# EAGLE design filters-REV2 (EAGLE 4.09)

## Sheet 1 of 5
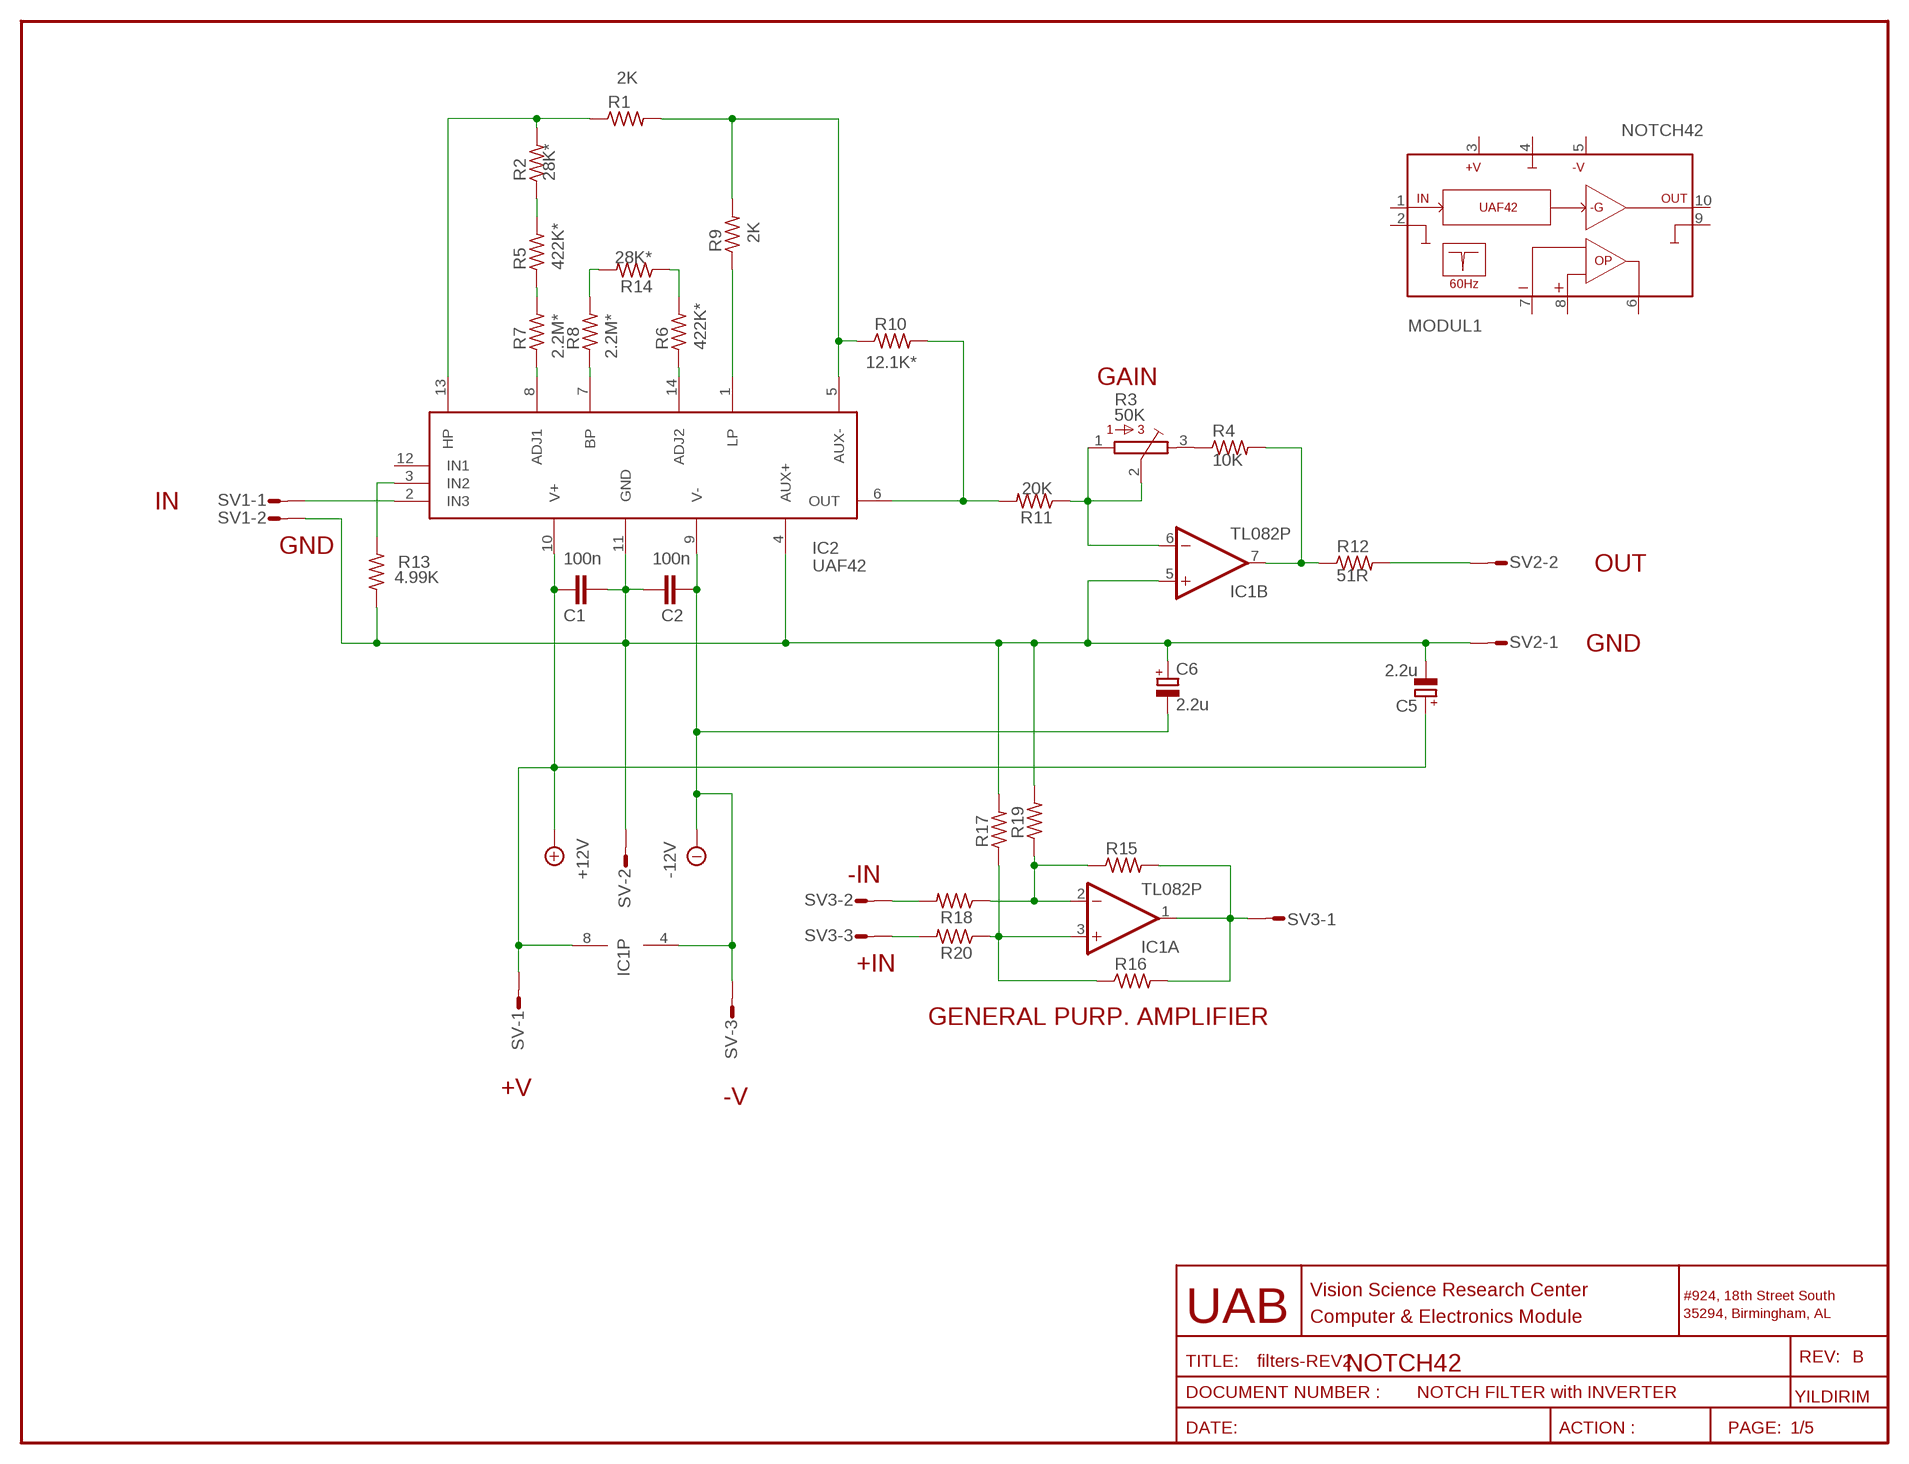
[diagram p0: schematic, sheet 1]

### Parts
C1  100n  C-EU050-025X075  [C050-025X075]
C2  100n  C-EU050-025X075  [C050-025X075]
C5  2.2u  CPOL-EUE2.5-5  [E2,5-5]
C6  2.2u  CPOL-EUE2.5-5  [E2,5-5]
IC1  TL082P  [DIL08]
IC2  UAF42  [DIP-14]
MODUL1  NOTCH42  [NOTCH42]
R1  2K  R-US_0207/10  [0207/10]
R2  28K*  R-US_0207/10  [0207/10]
R3  50K  B25P  [B25P@2]
R4  10K  R-US_0207/10  [0207/10]
R5  422K*  R-US_0207/10  [0207/10]
R6  422K*  R-US_0207/10  [0207/10]
R7  2.2M*  R-US_0207/10  [0207/10]
R8  2.2M*  R-US_0207/10  [0207/10]
R9  2K  R-US_0207/10  [0207/10]
R10  12.1K*  R-US_0207/10  [0207/10]
R11  20K  R-US_0207/10  [0207/10]
R12  51R  R-US_0207/10  [0207/10]
R13  4.99K  R-US_0207/10  [0207/10]
R14  28K*  R-US_0207/10  [0207/10]
R15  R-US_0207/10  [0207/10]
R16  R-US_0207/10  [0207/10]
R17  R-US_0207/10  [0207/10]
R18  R-US_0207/10  [0207/10]
R19  R-US_0207/10  [0207/10]
R20  R-US_0207/10  [0207/10]
SV  S03P  [S03P]
SV1  S02P  [S02P]
SV2  S02P  [S02P]
SV3  S03P  [S03P]

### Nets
+12VABI: C1.2 C5.+ IC1.8(P:V+) IC2.10(V+) SV.1 ; supply symbol labelled +12V
-12VABI: C2.1 C6.- IC1.4(P:V-) IC2.9(V-) SV.3 ; supply symbol labelled -12V
N$1: IC2.2(IN3) SV1.1
N$2: R12.2 SV2.2
N$3: R3.3 R4.1
N$4: C1.1 C2.2 C5.- C6.+ IC1.5(B:+IN) IC2.4(AUX+) IC2.11(GND) R13.1 R17.2 R19.2 SV1.2 SV2.1 SV.2
N$5: IC2.8(ADJ1) R7.1
N$6: R5.1 R7.2
N$7: IC2.7(BP) R8.1
N$8: IC1.7(B:OUT) R4.2 R12.1
N$9: IC1.6(B:-IN) R3.1 R3.2 R11.1
N$10: IC2.14(ADJ2) R6.1
N$11: R8.2 R14.2
N$12: R6.2 R14.1
N$13: R2.1 R5.2
N$14: R18.2 SV3.2
N$15: IC1.2(A:-IN) R15.1 R18.1 R19.1
N$16: R20.2 SV3.3
N$18: IC1.1(A:OUT) R15.2 R16.2 SV3.1
N$20: IC1.3(A:+IN) R16.1 R17.1 R20.1
N$52: IC2.3(IN2) R13.2
N$60: IC2.6(OUT) R10.2 R11.2
N$65: IC2.13(HP) R1.1 R2.2
N$68: IC2.5(AUX-) R1.2 R9.2 R10.1
N$69: IC2.1(LP) R9.1
Unconnected: IC2.12(IN1) MODUL1.1(IN) MODUL1.2(GND1) MODUL1.3(+V) MODUL1.4(COMM) MODUL1.5(-V) MODUL1.6(OP-OUT) MODUL1.7(OP-) MODUL1.8(OP+) MODUL1.9(GND2) MODUL1.10(OUT)

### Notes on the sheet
- GAIN
- IN
- GND
- OUT
- GND
- -IN
- +IN
- GENERAL PURP. AMPLIFIER
- +V
- -V
- B
- NOTCH42
- NOTCH FILTER with INVERTER

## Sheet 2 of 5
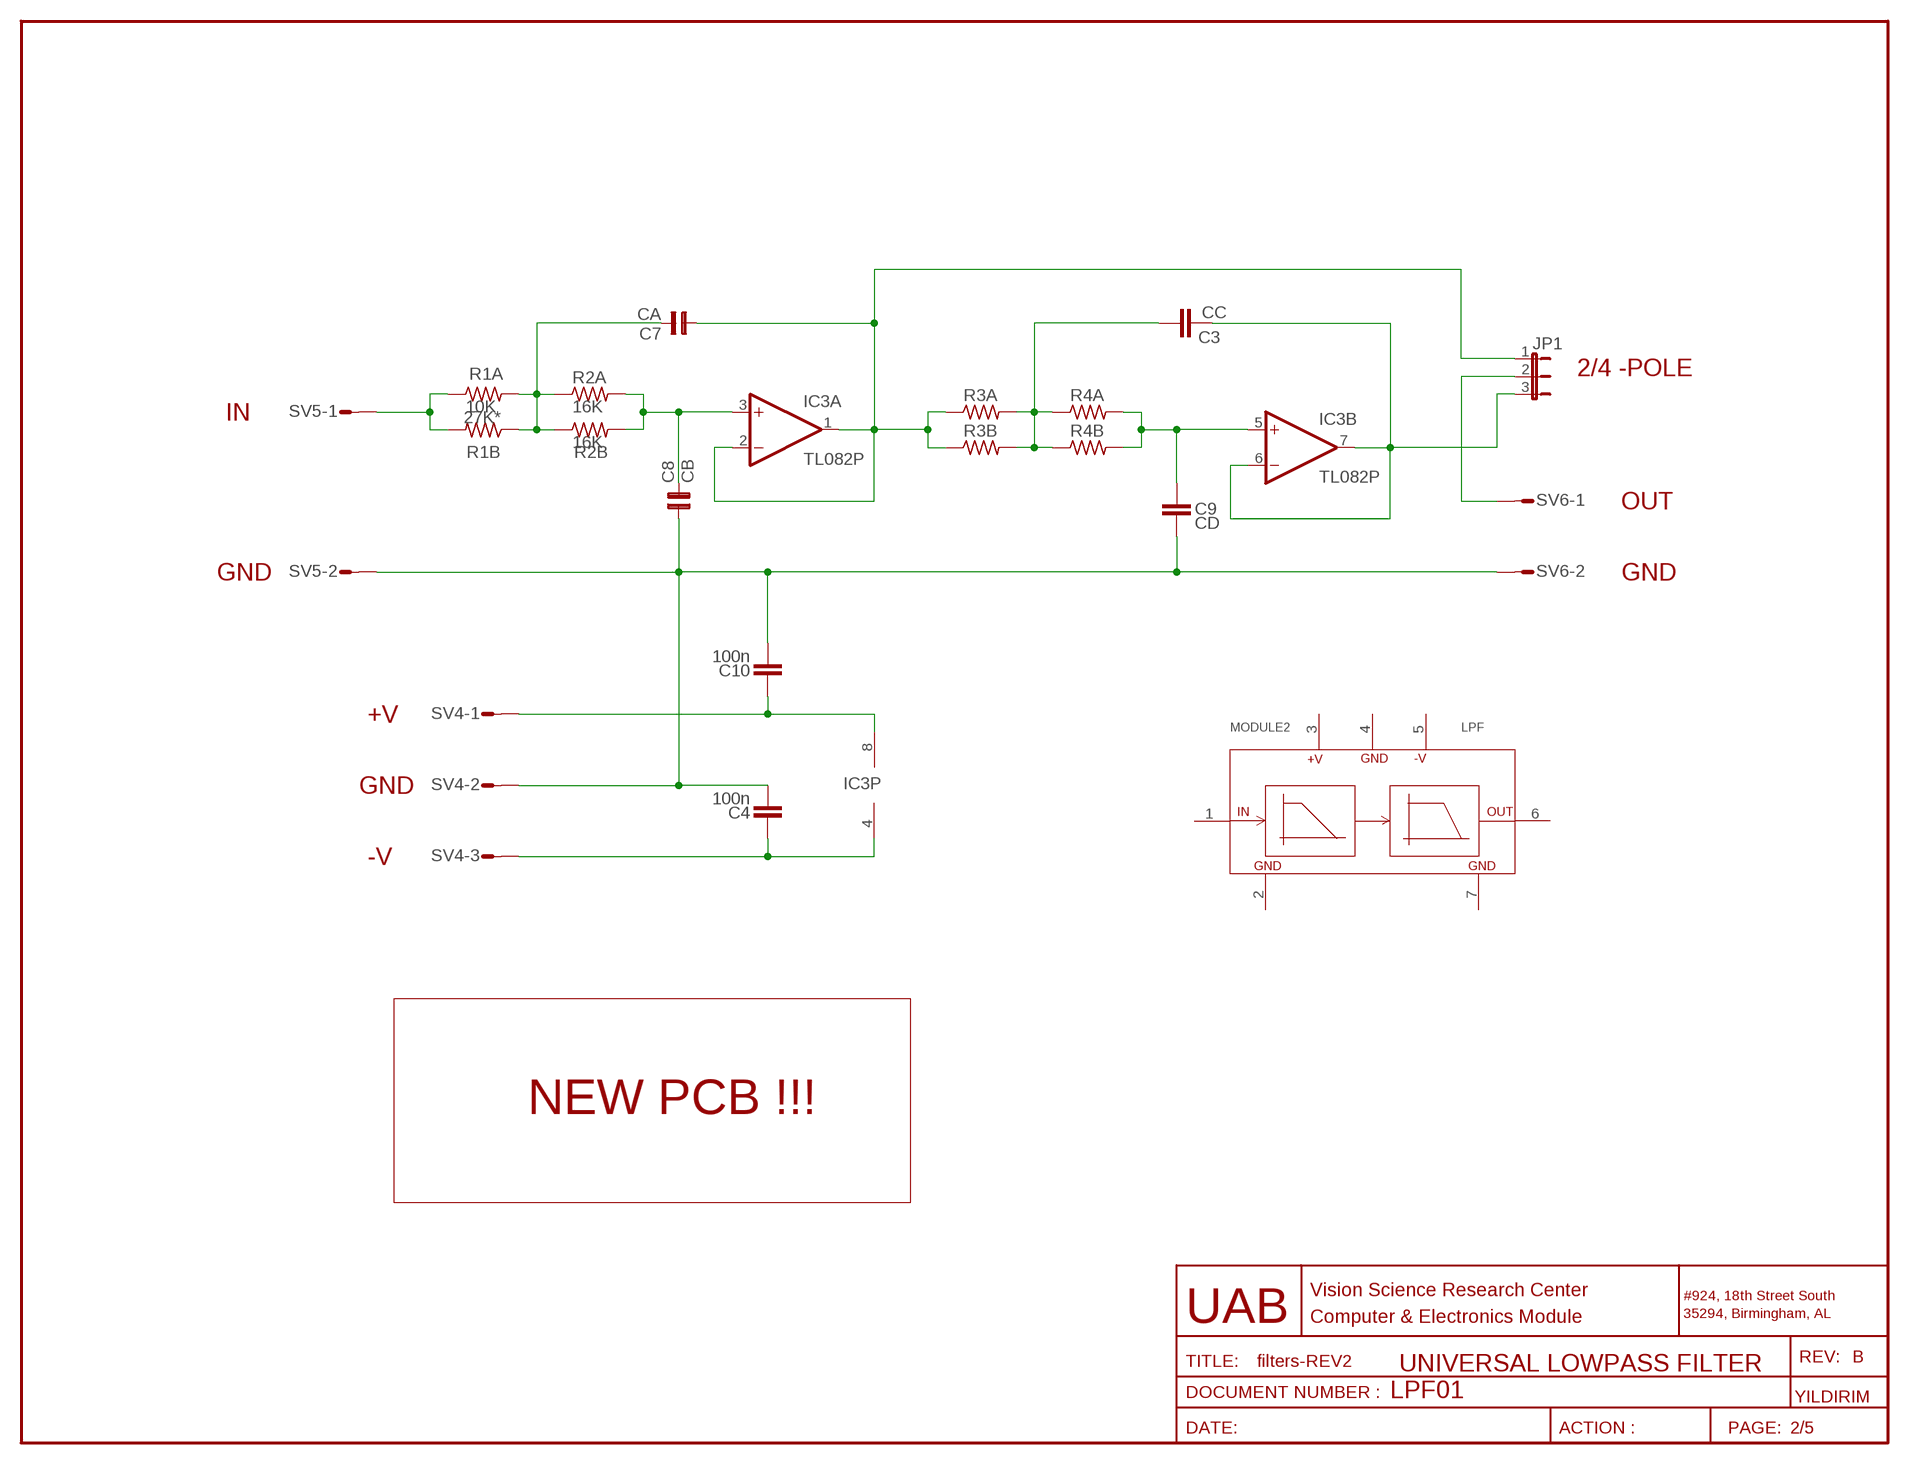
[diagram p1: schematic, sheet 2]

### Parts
C3  CC  C-EU050-025X075  [C050-025X075]
C4  100n  C-EU050-025X075  [C050-025X075]
C7  CA  C5/2.5  [C5B2.5]
C8  CB  C5/2.5  [C5B2.5]
C9  CD  C-EU050-025X075  [C050-025X075]
C10  100n  C-EU050-025X075  [C050-025X075]
IC3  TL082P  [DIL08]
JP1  JP2W  [JP2W]
MODULE2  LPF  [LPF]
R1A  10K  R-US_0207/10  [0207/10]
R1B  27K*  R-US_0207/10  [0207/10]
R2A  16K  R-US_0207/10  [0207/10]
R2B  16K  R-US_0207/10  [0207/10]
R3A  R-US_0207/10  [0207/10]
R3B  R-US_0207/10  [0207/10]
R4A  R-US_0207/10  [0207/10]
R4B  R-US_0207/10  [0207/10]
SV4  S03P  [S03P]
SV5  S02P  [S02P]
SV6  S02P  [S02P]

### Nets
N$17: JP1.2 SV6.1
N$19: C3.1 IC3.6(B:-IN) IC3.7(B:OUT) JP1.3
N$21: C7.2 R1A.2 R1B.1 R2A.1 R2B.1
N$22: C7.1 IC3.1(A:OUT) IC3.2(A:-IN) JP1.1 R3A.1 R3B.1
N$24: C8.2 IC3.3(A:+IN) R2A.2 R2B.2
N$25: C4.1 IC3.4(P:V-) SV4.3
N$26: C10.1 IC3.8(P:V+) SV4.1
N$30: C3.2 R3A.2 R3B.2 R4A.1 R4B.1
N$33: C9.1 IC3.5(B:+IN) R4A.2 R4B.2
N$42: C4.2 C8.1 C9.2 C10.2 SV4.2 SV5.2 SV6.2
SUM-OUT: R1A.1 R1B.2 SV5.1
Unconnected: MODULE2.1 MODULE2.2 MODULE2.3 MODULE2.4 MODULE2.5 MODULE2.6 MODULE2.7

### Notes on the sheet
- 2/4 -POLE
- IN
- OUT
- GND | GND
- +V
- GND
- -V
- NEW PCB !!!
- B
- UNIVERSAL LOWPASS FILTER
- LPF01

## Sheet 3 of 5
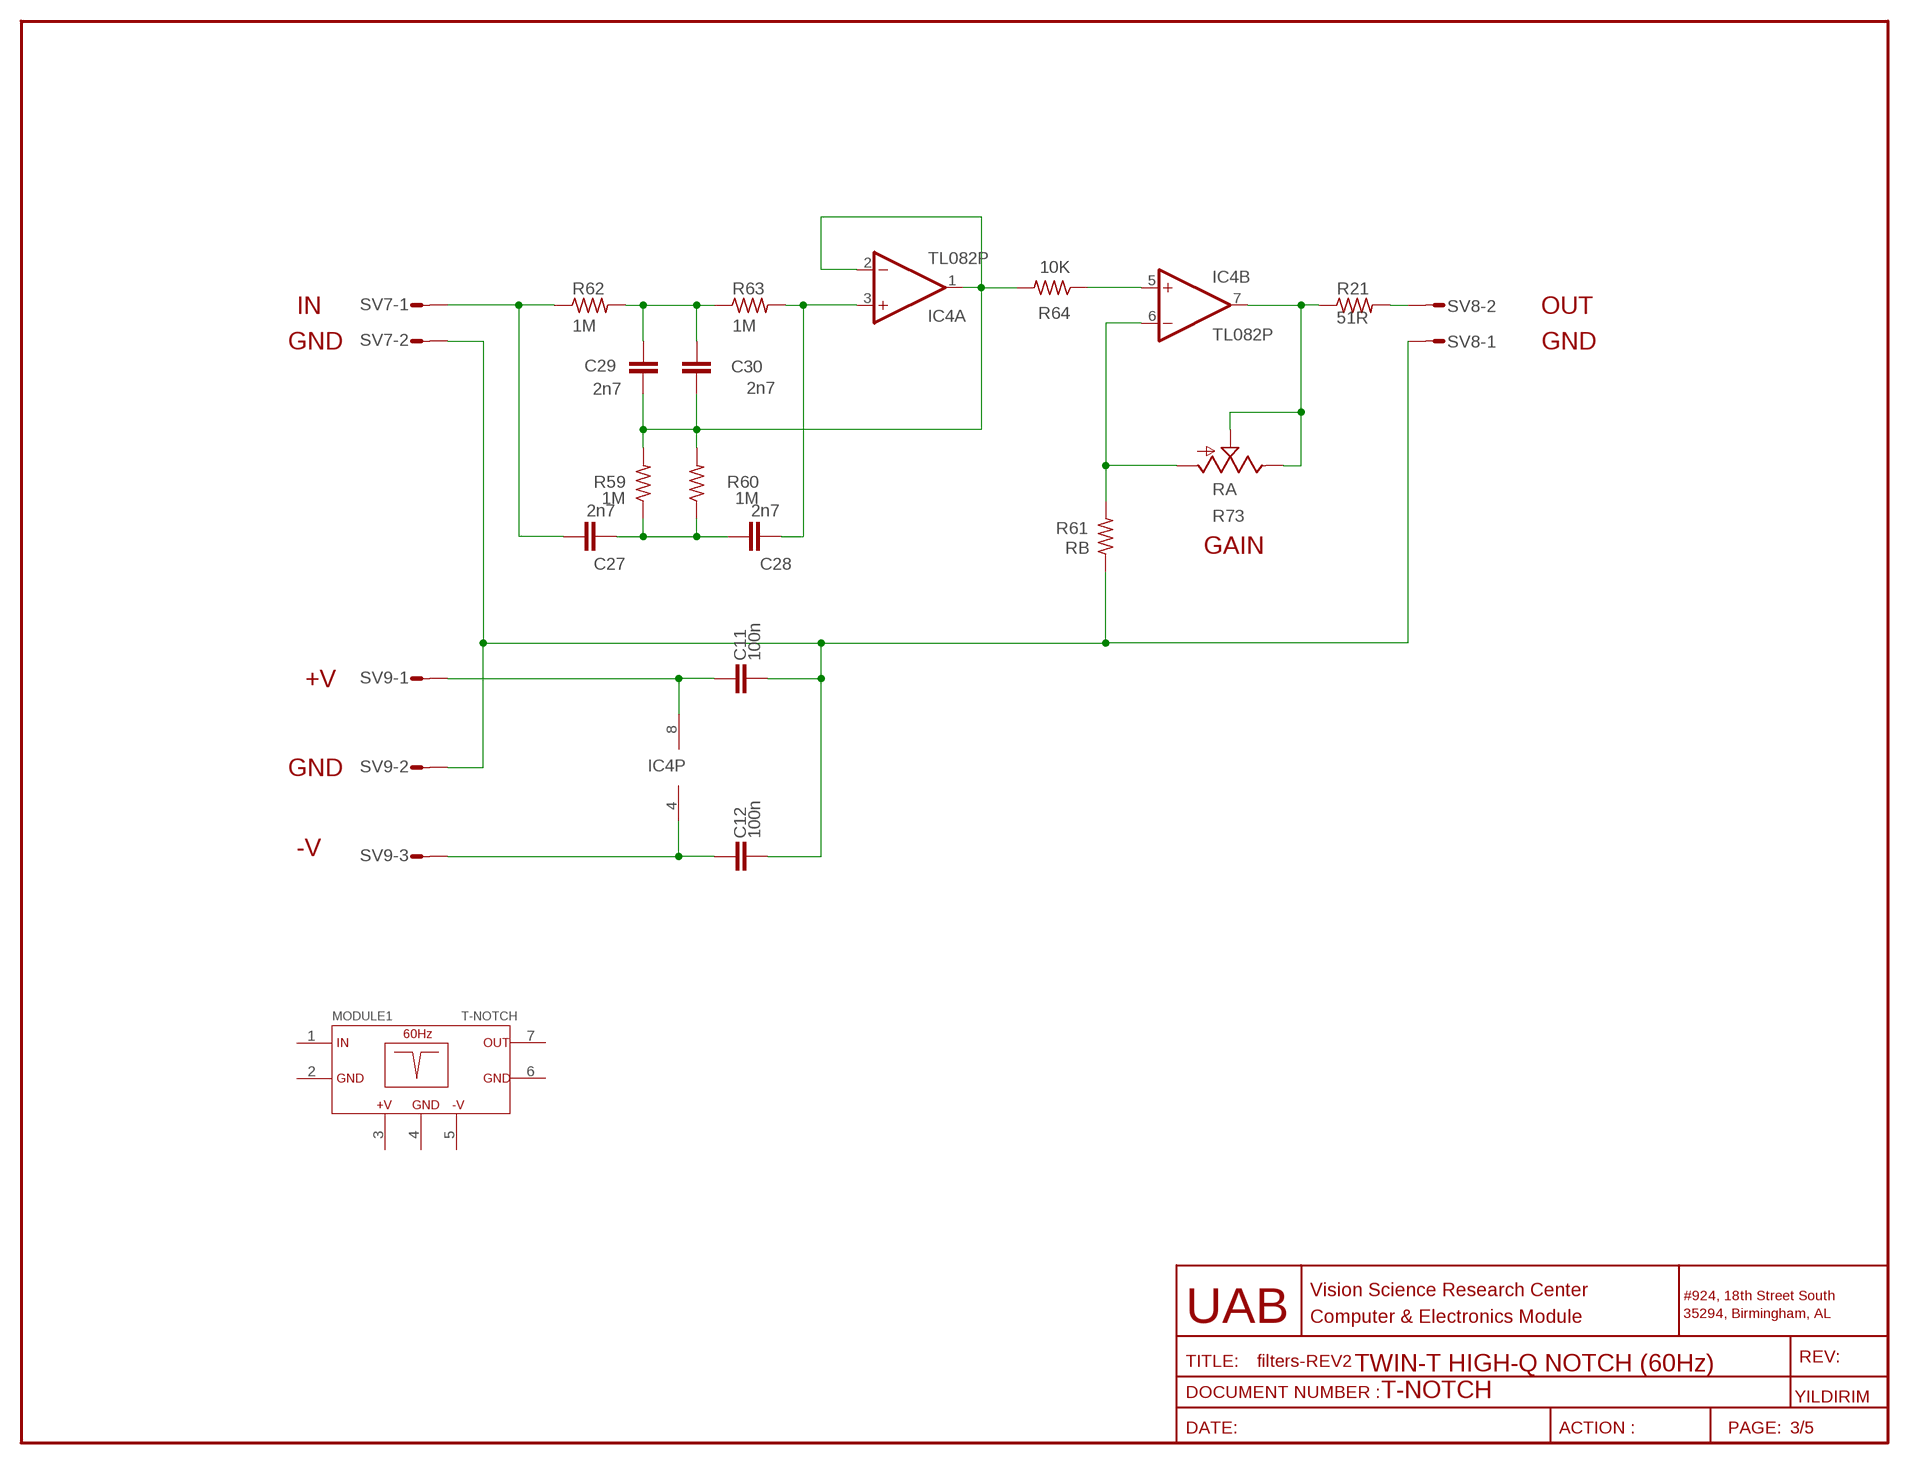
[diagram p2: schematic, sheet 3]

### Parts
C11  100n  C-EU050-025X075  [C050-025X075]
C12  100n  C-EU050-025X075  [C050-025X075]
C27  2n7  C-EU050-025X075  [C050-025X075]
C28  2n7  C-EU050-025X075  [C050-025X075]
C29  2n7  C-EU050-025X075  [C050-025X075]
C30  2n7  C-EU050-025X075  [C050-025X075]
IC4  TL082P  [DIL08]
MODULE1  T-NOTCH  [T-NOTCH]
R21  51R  R-US_0207/10  [0207/10]
R59  1M  R-US_0207/10  [0207/10]
R60  1M  R-US_0207/10  [0207/10]
R61  RB  R-US_0207/10  [0207/10]
R62  1M  R-US_0207/10  [0207/10]
R63  1M  R-US_0207/10  [0207/10]
R64  10K  R-US_0207/10  [0207/10]
R73  RA  TRIM_US-B25P  [B25P]
SV7  S02P  [S02P]
SV8  S02P  [S02P]
SV9  S03P  [S03P]

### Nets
N$23: C11.1 IC4.8(P:V+) SV9.1
N$27: C29.2 C30.2 R62.2 R63.1
N$28: C12.1 IC4.4(P:V-) SV9.3
N$31: C11.2 C12.2 R61.1 SV7.2 SV8.1 SV9.2
N$32: R21.2 SV8.2
N$34: IC4.7(B:OUT) R21.1 R73.E R73.S
N$35: IC4.5(B:+IN) R64.1
N$83: C27.2 R62.1 SV7.1
N$99: IC4.6(B:-IN) R61.2 R73.A
N$102: C27.1 C28.2 R59.1 R60.1
N$106: C28.1 IC4.3(A:+IN) R63.2
N$109: C29.1 C30.1 IC4.1(A:OUT) IC4.2(A:-IN) R59.2 R60.2 R64.2
Unconnected: MODULE1.1(IN) MODULE1.2(GND-IN) MODULE1.3(+V) MODULE1.4(GND) MODULE1.5(-V) MODULE1.6(GND-OUT) MODULE1.7(OUT)

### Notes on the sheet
- IN | OUT
- GND | GND
- GAIN
- +V
- GND
- -V
- TWIN-T HIGH-Q NOTCH (60Hz)
- T-NOTCH

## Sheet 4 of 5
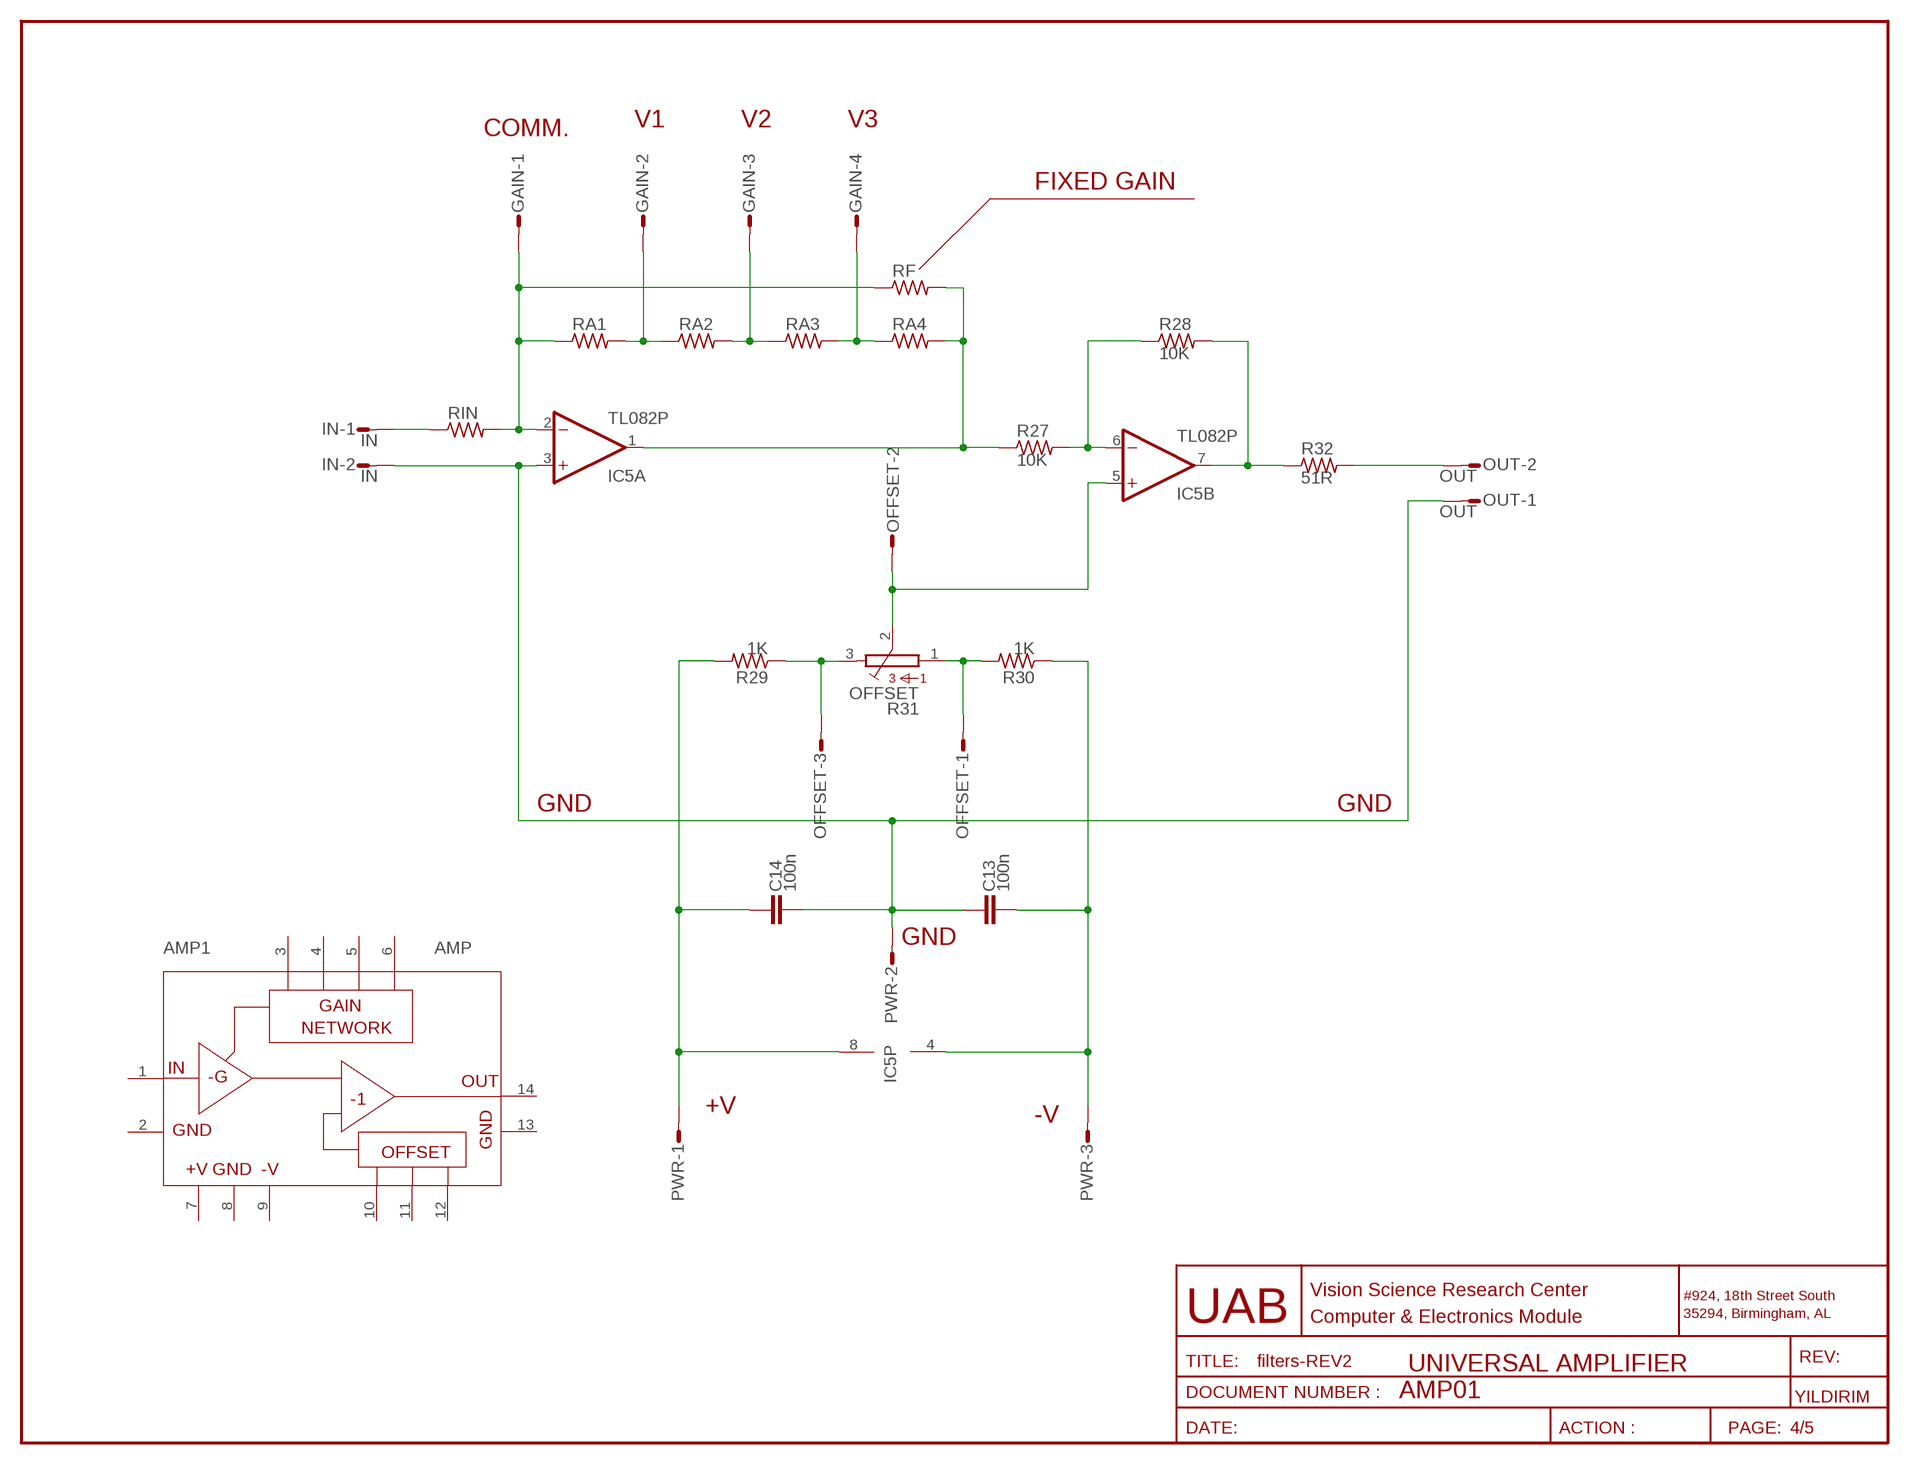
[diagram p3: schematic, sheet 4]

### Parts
AMP1  AMP  [AMP]
C13  100n  C-EU050-025X075  [C050-025X075]
C14  100n  C-EU050-025X075  [C050-025X075]
GAIN  S04P  [S04P]
IC5  TL082P  [DIL08]
IN  IN  S02P  [S02P]
OFFSET  S03P  [S03P]
OUT  OUT  S02P  [S02P]
PWR  S03P  [S03P]
R27  10K  R-US_0207/10  [0207/10]
R28  10K  R-US_0207/10  [0207/10]
R29  1K  R-US_0207/10  [0207/10]
R30  1K  R-US_0207/10  [0207/10]
R31  OFFSET  B25P  [B25P@2]
R32  51R  R-US_0207/10  [0207/10]
RA1  R-US_0207/10  [0207/10]
RA2  R-US_0207/10  [0207/10]
RA3  R-US_0207/10  [0207/10]
RA4  R-US_0207/10  [0207/10]
RF  R-US_0207/10  [0207/10]
RIN  R-US_0207/10  [0207/10]

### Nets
N$29: IN.1 RIN.1
N$36: GAIN.1 IC5.2(A:-IN) RA1.1 RF.1 RIN.2
N$37: GAIN.2 RA1.2 RA2.1
N$38: GAIN.3 RA2.2 RA3.1
N$39: GAIN.4 RA3.2 RA4.1
N$40: OUT.2 R32.2
N$41: C13.2 IC5.4(P:V-) PWR.3 R30.1
N$45: IC5.1(A:OUT) R27.1 RA4.2 RF.2
N$47: IC5.6(B:-IN) R27.2 R28.1
N$49: IC5.7(B:OUT) R28.2 R32.1
N$51: OFFSET.3 R29.1 R31.3
N$53: OFFSET.1 R30.2 R31.1
N$57: IC5.5(B:+IN) OFFSET.2 R31.2
N$58: C14.1 IC5.8(P:V+) PWR.1 R29.2
N$67: C13.1 C14.2 IC5.3(A:+IN) IN.2 OUT.1 PWR.2
Unconnected: AMP1.1 AMP1.2 AMP1.3 AMP1.4 AMP1.5 AMP1.6 AMP1.7 AMP1.8 AMP1.9 AMP1.10 AMP1.11 AMP1.12 AMP1.13 AMP1.14

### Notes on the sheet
- V1 | V2 | V3
- COMM.
- FIXED GAIN
- GND | GND
- GND
- +V
- -V
- UNIVERSAL AMPLIFIER
- AMP01

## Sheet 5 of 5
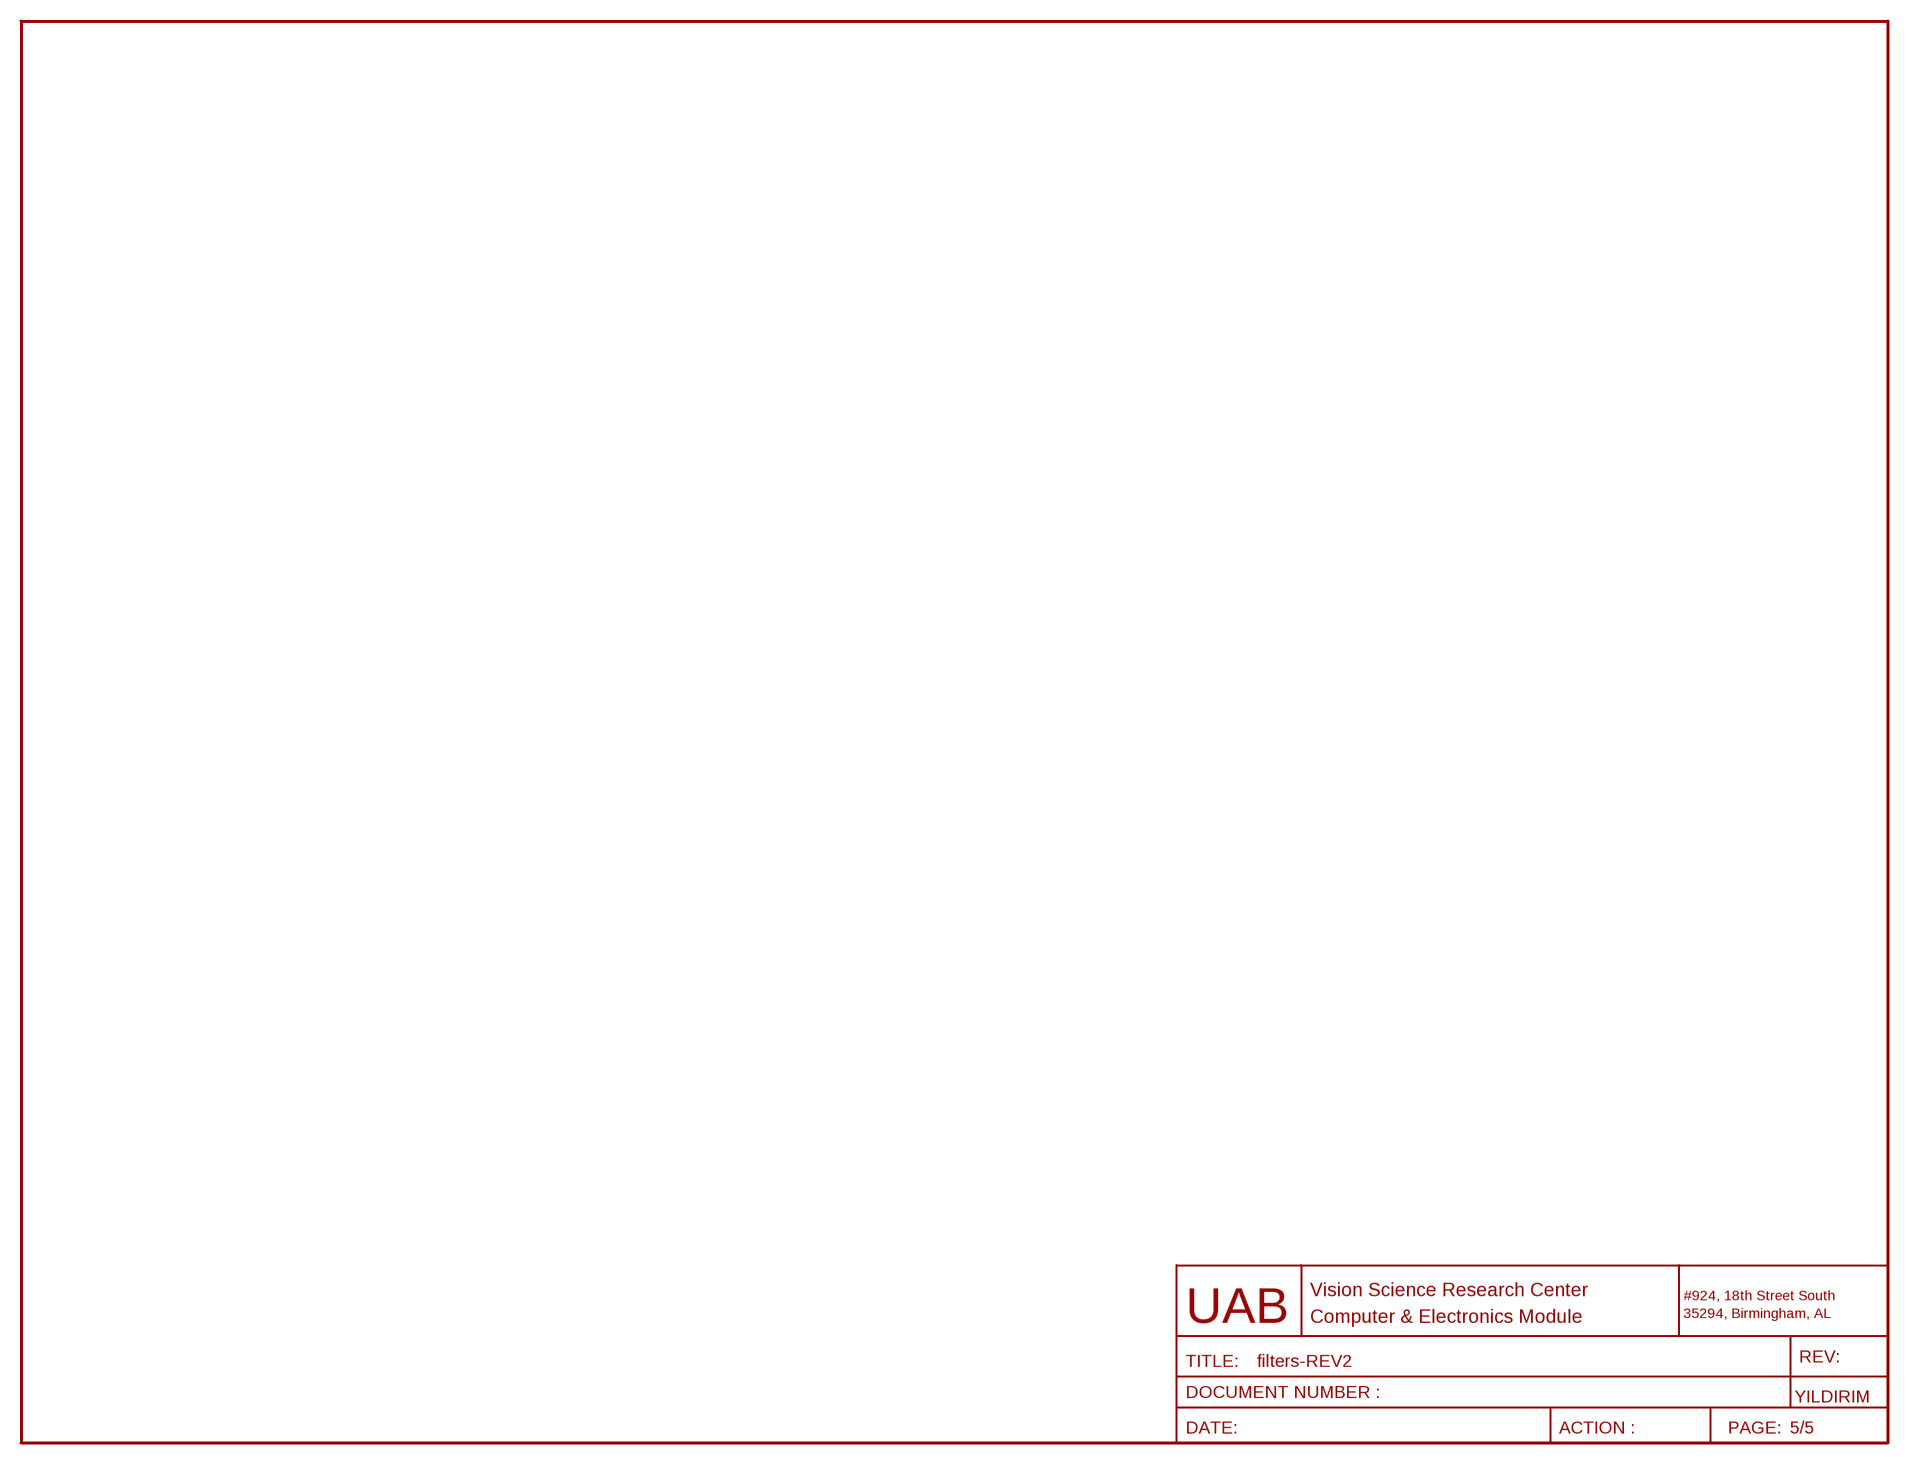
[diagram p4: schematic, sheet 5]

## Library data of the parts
AMP1 = ABI:AMP
C1-C4 C9-C14 C27-C30 = rcl:C-EU: CAPACITOR, European symbol
C5 C6 = rcl:CPOL-EU: POLARIZED CAPACITOR, European symbol
C7 C8 = capacitor-wima:C: CAPACITOR
GAIN = con-amp-mt:S04P: AMP MT CONNECTOR
IC1 IC3-IC5 = linear:TL082P: OP AMP
IC2 = burr-brown:UAF42: Universal Active Filter 100KHZ max
IN OUT SV1 SV2 SV5-SV8 = con-amp-mt:S02P: AMP MT CONNECTOR
JP1 = jumper:JP2W: JUMPER
MODUL1 = ABI:NOTCH42
MODULE1 = ABI:T-NOTCH
MODULE2 = ABI:LPF
OFFSET PWR SV SV3 SV4 SV9 = con-amp-mt:S03P: AMP MT CONNECTOR
R1 R1A R1B R2 R2A R2B R3A R3B R4 R4A R4B R5-R21 R27-R30 R32 R59-R64 RA1-RA4 RF RIN = rcl:R-US_: RESISTOR, American symbol
R3 R31 = pot:B25P: POTENTIOMETER
R73 = pot:TRIM_US-: POTENTIOMETER

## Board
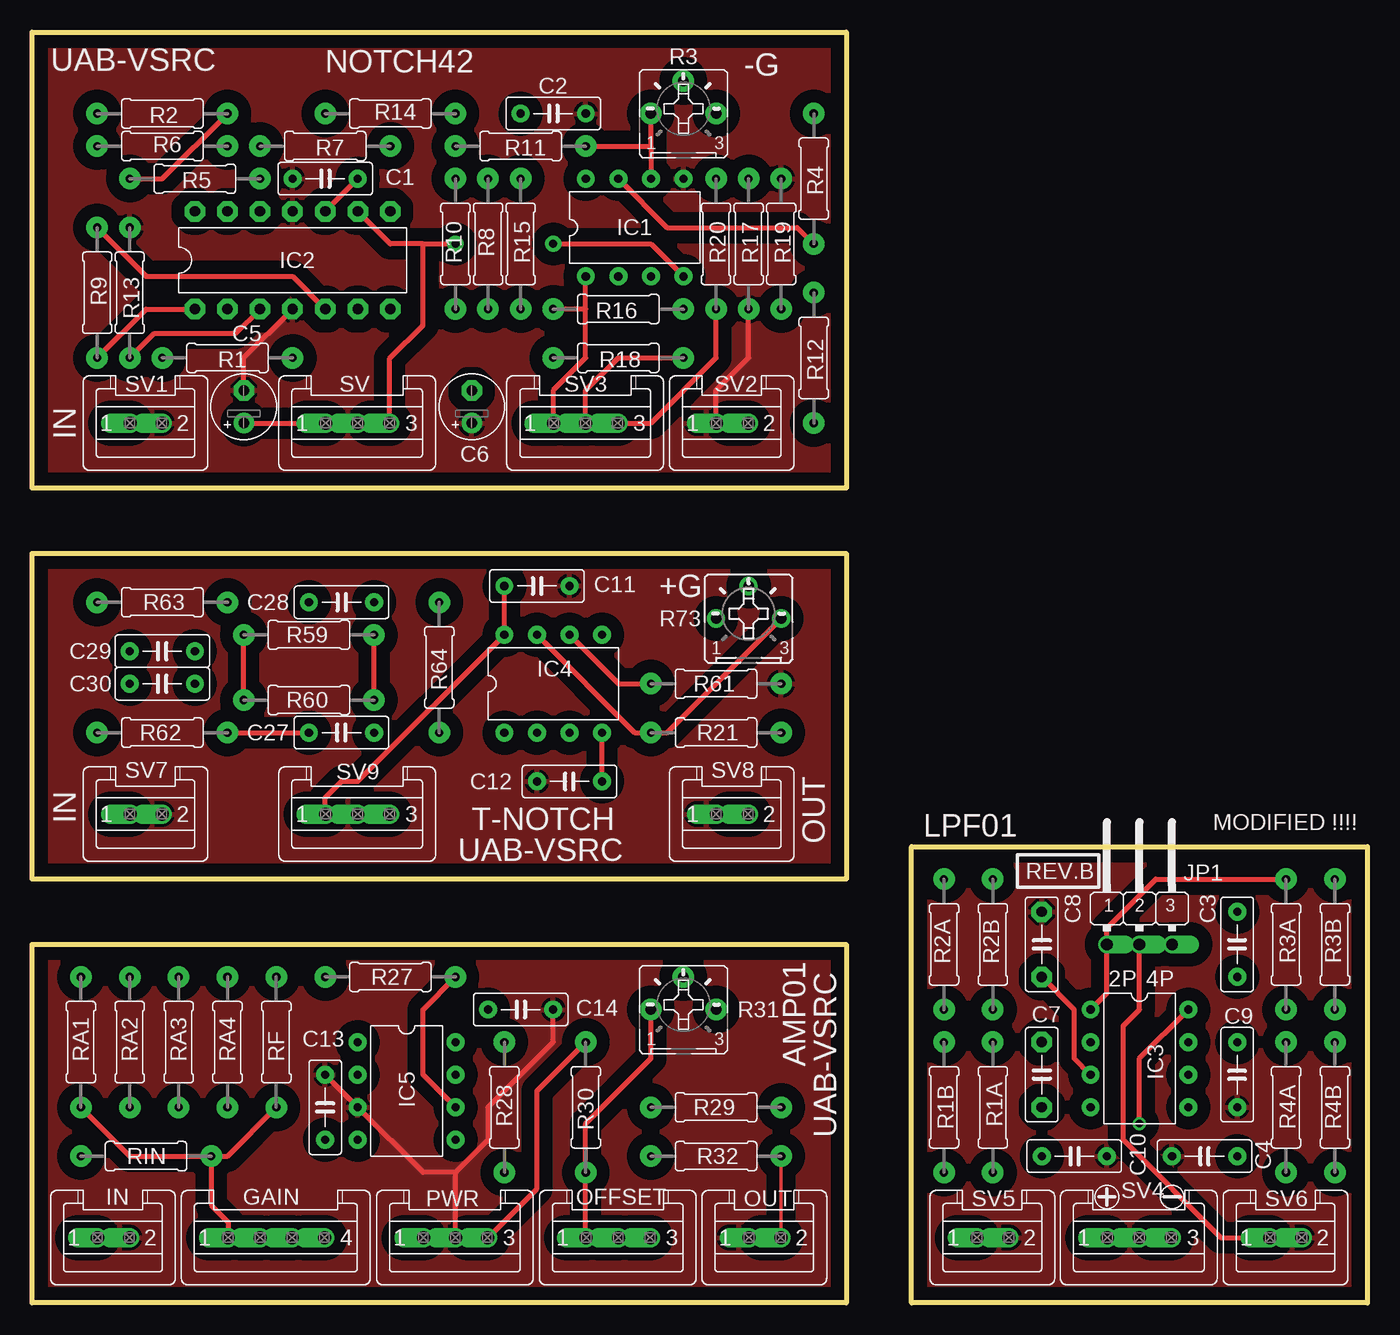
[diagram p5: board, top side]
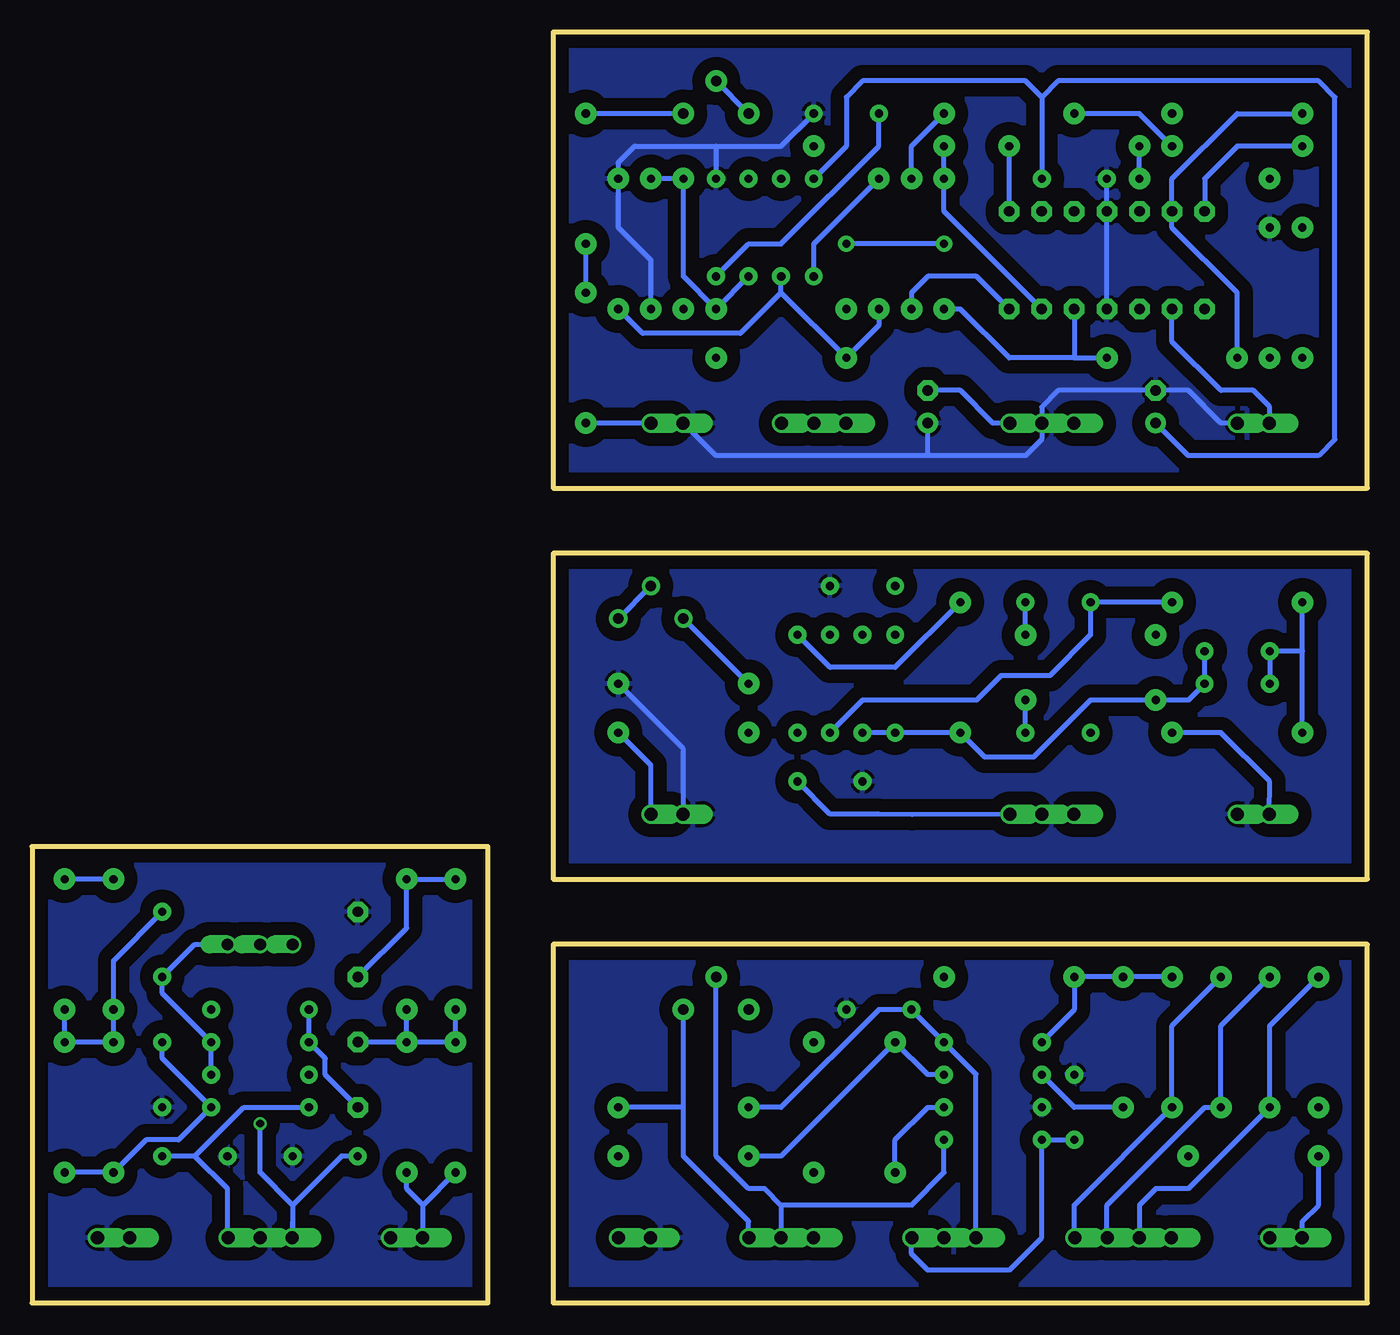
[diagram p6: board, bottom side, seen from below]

Size 104.14 x 99.06 mm. Coordinates in mm from the lower left corner, seen from the top.
Outline: 0,99.06 63.5,99.06 63.5,63.5 0,63.5 0,99.06
Outline: 68.58,35.56 104.14,35.56 104.14,0 68.58,0 68.58,35.56
Outline: 0,58.42 63.5,58.42 63.5,33.02 0,33.02 0,58.42
Outline: 0,27.94 63.5,27.94 63.5,0 0,0 0,27.94
Copper layers used: Top, Bottom

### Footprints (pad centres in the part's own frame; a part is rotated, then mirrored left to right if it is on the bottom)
AMP = drill 1.016 pad 1.778 round: 1 -30.48,0; 2 -27.94,0; 3 -20.32,0; 4 -17.78,0; 5 -15.24,0; 6 -12.7,0; 7 -5.08,0; 8 -2.54,0; 9 0,0; 10 7.62,0; 11 10.16,0; 12 12.7,0; 13 20.32,0; 14 22.86,0
C050-025X075 = drill 0.635 pad 1.397 round: 1 -2.54,0; 2 2.54,0
E2,5-5 = drill 0.813 pad 1.6 round: + -1.27,0 | drill 0.813 pad 1.6 octagon: - 1.27,0
C5B2.5 = drill 0.813 pad 1.6 octagon: 1 -2.54,0; 2 2.54,0
S04P = drill 1.016 offset: 1 3.75,0; 2 1.25,0; 3 -1.25,0; 4 -3.75,0
DIL08 = drill 0.635 pad 1.397 round: 1 -3.81,-3.81; 2 -1.27,-3.81; 3 1.27,-3.81; 4 3.81,-3.81; 5 3.81,3.81; 6 1.27,3.81; 7 -1.27,3.81; 8 -3.81,3.81
DIP-14 = drill 0.813 pad 1.6 octagon: 1 -7.62,-3.81; 2 -5.08,-3.81; 3 -2.54,-3.81; 4 0,-3.81; 5 2.54,-3.81; 6 5.08,-3.81; 7 7.62,-3.81; 8 7.62,3.81; 9 5.08,3.81; 10 2.54,3.81; 11 0,3.81; 12 -2.54,3.81; 13 -5.08,3.81; 14 -7.62,3.81
S02P = drill 1.016 offset: 1 1.25,0; 2 -1.25,0
JP2W = drill 0.914 offset: 1 -2.54,-1.27; 2 0,-1.27; 3 2.54,-1.27
NOTCH42 = drill 1.016 pad 1.778 round: 1 -22.86,0; 2 -20.32,0; 3 -7.62,0; 4 -5.08,0; 5 -2.54,0; 6 10.16,0; 7 12.7,0; 8 15.24,0; 9 22.86,0; 10 25.4,0
T-NOTCH = drill 1.016 pad 1.778 round: 1 -24.13,0; 2 -21.59,0; 3 -8.89,0; 4 -6.35,0; 5 -3.81,0; 6 21.59,0; 7 24.13,0
LPF = drill 1.016 pad 1.676 round: 1 -12.7,0; 2 -10.16,0; 3 -2.54,0; 4 0,0; 5 2.54,0; 6 10.16,0; 7 12.7,0
S03P = drill 1.016 offset: 1 2.5,0; 2 0,0; 3 -2.5,0
0207/10 = drill 0.635 pad 1.676 round: 1 -5.08,0; 2 5.08,0
B25P@2 = drill 0.813 pad 1.676 round: 1 -2.54,0; 2 0,2.54; 3 2.54,0
B25P = drill 0.813 pad 1.422 round: A -2.54,0; E 2.54,0; S 0,2.54

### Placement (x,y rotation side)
AMP1  not placed on the board
C1  22.86,87.63 0 top
C2  40.64,92.71 0 top
C3  93.98,27.94 90 top
C4  91.44,11.43 180 top
C5  16.51,69.85 90 top
C6  34.29,69.85 90 top
C7  78.74,17.78 90 top
C8  78.74,27.94 270 top
C9  93.98,17.78 270 top
C10  81.28,11.43 0 top
C11  39.37,55.88 0 top
C12  41.91,40.64 180 top
C13  22.86,15.24 270 top
C14  38.1,22.86 0 top
C27  24.13,44.45 180 top
C28  24.13,54.61 0 top
C29  10.16,50.8 180 top
C30  10.16,48.26 180 top
GAIN  19.05,5.08 180 top
IC1  46.99,83.82 0 top
IC2  20.32,81.28 0 top
IC3  86.36,19.05 270 top
IC4  40.64,48.26 0 top
IC5  29.21,16.51 270 top
IN  6.35,5.08 180 top
JP1  86.36,29.21 0 top
MODUL1  not placed on the board
MODULE1  not placed on the board
MODULE2  not placed on the board
OFFSET  45.72,5.08 180 top
OUT  57.15,5.08 180 top
PWR  33.02,5.08 180 top
R1  15.24,73.66 0 top
R1A  74.93,15.24 90 top
R1B  71.12,15.24 270 top
R2  10.16,92.71 180 top
R2A  71.12,27.94 90 top
R2B  74.93,27.94 90 top
R3  50.8,92.71 0 top
R3A  97.79,27.94 270 top
R3B  101.6,27.94 270 top
R4  60.96,87.63 270 top
R4A  97.79,15.24 270 top
R4B  101.6,15.24 270 top
R5  12.7,87.63 180 top
R6  10.16,90.17 0 top
R7  22.86,90.17 180 top
R8  35.56,82.55 90 top
R9  5.08,78.74 90 top
R10  33.02,82.55 90 top
R11  38.1,90.17 180 top
R12  60.96,73.66 270 top
R13  7.62,78.74 270 top
R14  27.94,92.71 0 top
R15  38.1,82.55 90 top
R16  45.72,77.47 180 top
R17  55.88,82.55 270 top
R18  45.72,73.66 0 top
R19  58.42,82.55 90 top
R20  53.34,82.55 270 top
R21  53.34,44.45 0 top
R27  27.94,25.4 0 top
R28  36.83,15.24 90 top
R29  53.34,15.24 180 top
R30  43.18,15.24 270 top
R31  50.8,22.86 0 top
R32  53.34,11.43 0 top
R59  21.59,52.07 180 top
R60  21.59,46.99 180 top
R61  53.34,48.26 180 top
R62  10.16,44.45 180 top
R63  10.16,54.61 0 top
R64  31.75,49.53 270 top
R73  55.88,53.34 0 top
RA1  3.81,20.32 90 top
RA2  7.62,20.32 90 top
RA3  11.43,20.32 90 top
RA4  15.24,20.32 90 top
RF  19.05,20.32 90 top
RIN  8.89,11.43 0 top
SV  25.4,68.58 180 top
SV1  8.89,68.58 180 top
SV2  54.61,68.58 180 top
SV3  43.18,68.58 180 top
SV4  86.36,5.08 180 top
SV5  74.93,5.08 180 top
SV6  97.79,5.08 180 top
SV7  8.89,38.1 180 top
SV8  54.61,38.1 180 top
SV9  25.4,38.1 180 top

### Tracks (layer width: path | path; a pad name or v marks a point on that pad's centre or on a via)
+12VABI
  Top 0.406: C1.2 IC2.10 | C5.+ SV.1
  Bottom 0.406: C5.+ 13.97,66.04 3.81,66.04 2.54,67.31 2.54,93.98 3.81,95.25 24.13,95.25 25.4,93.98 | 25.4,93.98 C1.2 | IC1.8 40.64,90.17 40.64,93.98 39.37,95.25 26.67,95.25 25.4,93.98
-12VABI  (via drill 0.61 pad 1.27)
  Top 0.406: SV.3 27.9,73.62 30.48,76.2 30.48,82.55 | 30.48,82.55 27.94,82.55 IC2.9 | IC1.4 48.26,82.55 v40.64,82.55 | 30.48,82.55 v33.02,82.55
  Bottom 0.406: SV.3 29.21,68.58 31.75,71.12 C6.- | C2.1 38.1,90.17 45.72,82.55 48.26,82.55 IC1.4 | v33.02,82.55 v40.64,82.55
N$1
  Bottom 0.406: IC2.2 15.24,74.93 11.43,71.12 8.89,71.12 7.62,69.85 SV1.1
N$2
  Bottom 0.406: SV2.2 R12.2
N$3
  Bottom 0.406: R3.3 R4.1
N$4
  Top 0.406: IC2.4 16.51,73.66 C5.- | R17.2 55.88,73.66 53.34,71.12 53.34,68.58 SV2.1
  Bottom 0.406: C1.1 IC2.11 IC2.4 | C2.2 45.72,90.17 50.8,90.17 | 50.8,90.17 IC1.5 | SV1.2 11.43,68.58 13.97,71.12 C5.- 24.13,71.12 25.4,69.85 SV.2 25.4,67.31 26.67,66.04 34.29,66.04 | 34.29,66.04 50.8,66.04 53.34,68.58 SV2.1 | 34.29,66.04 C6.+ | 50.8,90.17 57.15,90.17 58.42,88.9 R19.2 58.42,83.82 55.88,81.28 R17.2
  pour Top (isolate 1.016): 0,99.06 63.5,99.06 63.5,63.5 0,63.5
  pour Bottom (isolate 1.016): 0,99.06 63.5,99.06 63.5,63.5 0,63.5
N$5
  Bottom 0.406: IC2.8 R7.1
N$6
  Bottom 0.406: R5.1 R7.2
N$7
  Bottom 0.406: IC2.7 30.48,80.01 34.29,80.01 35.56,78.74 R8.1
N$8
  Top 0.406: IC1.7 49.53,83.82 59.69,83.82 R4.2
  Bottom 0.406: R4.2 R12.1
N$9
  Top 0.406: 48.26,90.17 IC1.6 | 48.26,90.17 R3.1 | R11.1 48.26,90.17
  Bottom 0.406: R3.1 R3.2
N$10
  Bottom 0.406: IC2.14 12.7,87.63 10.16,90.17 R6.1
N$11
  Bottom 0.406: R14.2 35.56,90.17 R8.2
N$12
  Bottom 0.406: R6.2 17.78,92.71 R14.1
N$13
  Top 0.406: R5.2 10.16,87.63 R2.1
N$14
  Top 0.406: R18.2 45.72,73.66 43.18,71.12 SV3.2
N$15
  Bottom 0.406: R15.1 38.1,76.2 R18.1 45.72,78.74 | 45.72,78.74 IC1.2 | R19.1 56.52,75.56 48.9,75.56 45.72,78.74
N$16
  Top 0.406: R20.2 53.34,73.66 48.26,68.58 SV3.3
N$17
  Top 0.406: SV6.1 92.71,5.08 85.09,12.7 85.09,21.59 86.36,22.86 JP1.2
N$18
  Top 0.406: SV3.1 40.68,71.16 43.18,73.66 43.18,77.47 | 43.18,77.47 R16.2 | 43.18,77.47 IC1.1
  Bottom 0.406: R15.2 43.18,82.55 IC1.1
N$19
  Bottom 0.406: JP1.3 91.44,27.94 C3.1 93.98,24.13 IC3.7 IC3.6
N$20
  Bottom 0.406: IC1.3 R16.1 53.34,80.01 R20.1 R17.1
N$21
  Bottom 0.406: R1A.2 R1B.1 R2A.1 | R1A.2 C7.2 | R1A.2 R2B.1
N$22
  Top 0.406: R3A.1 87.63,33.02 83.82,29.21 JP1.1 83.82,24.13 IC3.1
  Bottom 0.406: R3A.1 R3B.1 | C7.1 81.28,17.78 81.28,19.05 IC3.2 IC3.1
N$23
  Top 0.406: C11.1 IC4.8 25.4,40.64 24.13,40.64 22.86,39.37 22.86,38.1 SV9.1
N$24
  Top 0.406: C8.2 81.28,22.86 81.28,19.05 IC3.3
  Bottom 0.406: R2A.2 R2B.2 74.93,29.21 C8.2
N$25
  Bottom 0.406: IC3.4 87.63,15.24 91.44,11.43 | 91.44,11.43 C4.1 | 91.44,11.43 88.9,8.89 88.9,6.35 SV4.3
N$26  (via drill 0.61)
  Top 0.406: IC3.8 86.36,19.05 v86.36,13.97
  Bottom 0.406: C10.1 80.01,11.43 83.82,7.62 | 83.82,7.62 SV4.1 | v86.36,13.97 86.36,10.16 83.82,7.62 | 83.82,7.62 83.82,5.08
N$27
  Bottom 0.406: C30.2 C29.2 5.08,50.8 | R62.2 5.08,50.8 | 5.08,50.8 R63.1
N$28
  Top 0.406: C12.1 IC4.4
  Bottom 0.406: SV9.3 35.52,38.06 38.1,38.1 41.91,38.1 C12.1
N$29
  Bottom 0.406: RIN.1 3.81,7.62 5.08,6.35 IN.1
N$30
  Bottom 0.406: R3B.2 R4B.1 R4A.1 R3A.2 97.79,26.67 C3.2
N$31
  Bottom 0.406: R61.1 53.34,43.18 53.34,39.37 SV8.1
  pour Bottom (isolate 1.016): 0,58.42 63.5,58.42 63.5,33.02 0,33.02
  pour Top (isolate 1.016): 0,58.42 63.5,58.42 63.5,33.02 0,33.02
N$32
  Bottom 0.406: R21.2 55.88,41.91 55.88,39.37 SV8.2
N$33
  Bottom 0.406: R4B.2 R4A.2 95.25,12.7 92.71,12.7 IC3.5 93.98,19.05 C9.1
N$34
  Top 0.406: R73.E 49.53,44.45 R21.1 46.99,44.45 IC4.7
  Bottom 0.406: R73.E R73.S
N$35
  Bottom 0.406: IC4.5 41.91,49.53 36.83,49.53 R64.1
N$36
  Top 0.406: GAIN.1 15.3,6.29 13.97,7.62 RIN.2 | RA1.1 7.62,11.43 RIN.2 | RIN.2 15.24,11.43 RF.1
  Bottom 0.406: IC5.2 22.86,15.24 RF.1
N$37
  Bottom 0.406: RA1.2 7.62,21.59 RA2.1 13.97,8.89 16.51,8.89 17.78,7.62 17.78,5.08 GAIN.2
N$38
  Bottom 0.406: RA2.2 11.43,21.59 RA3.1 12.7,15.24 20.32,7.62 20.32,5.08 GAIN.3
N$39
  Bottom 0.406: RA3.2 15.24,21.59 RA4.1 22.86,7.62 22.86,5.08 GAIN.4
N$40
  Top 0.254: R32.2 58.42,6.35 OUT.2
N$41
  Top 0.406: R30.1 39.37,16.51 39.37,8.89 35.56,5.08 PWR.3
  Bottom 0.406: C13.2 IC5.4 25.4,5.08 27.94,2.54 34.29,2.54 35.56,3.81 35.56,5.08 PWR.3
N$42
  pour Top (isolate 1.016): 68.58,35.56 104.14,35.56 104.14,0 68.58,0
  pour Bottom (isolate 1.016): 68.58,35.56 104.14,35.56 104.14,0 68.58,0
N$45
  Bottom 0.406: RA4.2 RF.2 R27.1 22.86,22.86 IC5.1
N$47
  Top 0.406: R27.2 30.48,22.86 30.48,17.78 IC5.6
  Bottom 0.406: IC5.6 34.29,15.24 36.83,12.7 R28.1
N$49
  Bottom 0.406: IC5.7 34.29,17.78 R28.2 45.72,11.43 R32.1
N$51
  Bottom 0.406: 53.34,15.24 R31.3 | 53.34,15.24 R29.1 | 53.34,15.24 53.34,11.43 48.26,6.35 OFFSET.3
N$52
  Top 0.406: R13.2 9.53,75.56 15.88,75.56 IC2.3
N$53
  Top 0.406: OFFSET.1 43.18,6.35 R30.2 43.18,13.97 48.26,19.05 R31.1
N$57
  Bottom 0.406: R31.2 50.8,11.43 48.26,8.89 46.99,8.89 45.72,7.62 | IC5.5 33.02,10.16 35.56,7.62 45.72,7.62 | 45.72,7.62 OFFSET.2
N$58
  Bottom 0.406: PWR.1 30.52,17.82 IC5.8 C14.1 38.1,22.86 45.72,15.24 R29.2
N$60
  Bottom 0.406: IC2.6 33.02,85.09 R10.2 R11.2
N$65
  Bottom 0.406: R2.2 10.16,92.71 15.24,87.63 IC2.13 15.24,83.82 10.16,78.74 R1.1
N$67
  Top 0.406: C13.1 IC5.3 30.48,10.16 33.02,10.16 | C14.2 40.64,20.32 35.56,15.24 35.56,12.7 33.02,10.16 | PWR.2 33.02,10.16
  pour Bottom (isolate 1.016): 0,27.94 63.5,27.94 63.5,0 0,0
  pour Top (isolate 1.016): 0,27.94 63.5,27.94 63.5,0 0,0
N$68
  Top 0.406: R9.2 8.89,80.01 20.32,80.01 IC2.5
  Bottom 0.406: 22.86,73.66 R1.2 | IC2.5 22.86,73.66 | 22.86,73.66 27.94,73.66 31.75,77.47 R10.1
N$69
  Top 0.406: IC2.1 8.89,77.47 R9.1
N$83
  Top 0.406: R62.1 C27.2
  Bottom 0.406: R62.1 11.43,44.45 7.62,40.64 SV7.1
N$99
  Top 0.406: IC4.6 45.72,48.26 R61.2
  Bottom 0.406: R61.2 R73.A
N$102
  Top 0.406: R60.1 R59.1
  Bottom 0.406: C27.1 R60.1 | R59.1 C28.2
N$106
  Bottom 0.406: R63.2 C28.1 21.59,52.07 24.77,48.9 28.57,48.9 30.48,46.99 39.37,46.99 IC4.3
N$109
  Top 0.406: R60.2 R59.2
  Bottom 0.406: C29.1 C30.1 13.97,46.99 R60.2 21.59,46.99 26.04,42.55 29.84,42.55 R64.2 IC4.1 IC4.2
SUM-OUT
  Bottom 0.406: 73.66,7.62 R1B.2 | 73.66,7.62 74.93,8.89 R1A.1 | 73.66,7.62 73.66,6.35 SV5.1

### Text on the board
tPlace: UAB-VSRC | NOTCH42 | -G | IN | +G | OUT | IN | LPF01 | T-NOTCH | MODIFIED !!!! | UAB-VSRC | REV.B | UAB-VSRC | 2P | 4P | AMP01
